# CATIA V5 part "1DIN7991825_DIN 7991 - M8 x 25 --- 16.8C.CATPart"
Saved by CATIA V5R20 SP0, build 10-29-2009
Part number: 1DIN7991825_DIN 7991 - M8 x 25 --- 16.8C
Revision: ANY
Definition: UNKNOWN
Nomenclature: 1DIN7991825_DIN 7991 - M8 x 25 --- 16.8C
Source: Unknown
Bounding box of the stored display mesh (mm): x 0 to 25, y -7.59 to 7.59, z -7.785 to 7.785
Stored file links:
  C:\Users\Utente\Desktop\IO LAVORO\3D X SITO CF\CUMSA\3D files RC\RC 205010\1DIN7991825_DIN 7991 - M8 x 25 --- 16.8C.CATPart
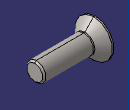
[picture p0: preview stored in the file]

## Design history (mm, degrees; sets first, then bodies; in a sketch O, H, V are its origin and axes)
Body1 "Hex" (main body)
  Solid1: solid without history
